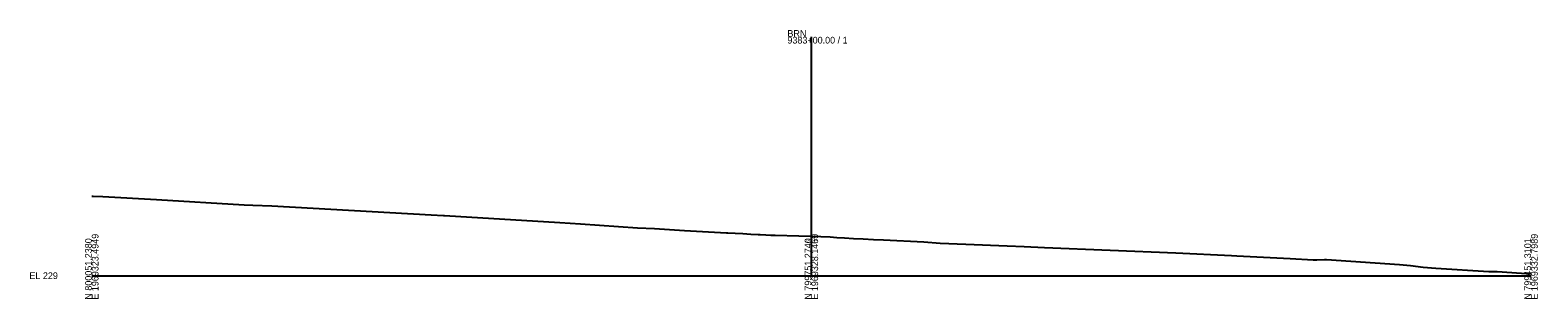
# Model space of a CAD drawing. Extents: x -26 to 2603, y -10 to 49639.
# Drawn here: x 1974 to 2603, y 26490 to 26603 of the extents above; entities that cross this region are included whole.
import ezdxf

# ---------------------------------------------------------------- set-up
doc = ezdxf.new("R2010")
doc.units = 0
for name, color, linetype in [('Default', 7, 'Continuous'), ('RD_GPK_XS_Cell', 7, 'Continuous'), ('RD_XS_ExGround', 7, 'Continuous'), ('RD_XS_TX_Elev_EX', 7, 'Continuous')]:
    doc.layers.add(name, color=color, linetype=linetype)

msp = doc.modelspace()

# ---------------------------------------------------------------- linework, layer by layer
at = {"layer": 'RD_GPK_XS_Cell'}
for p, q in [((2300, 26500), (2300, 26599.72)), ((2000, 26500), (2300, 26500)), ((2300, 26500), (2600, 26500))]:
    msp.add_line(p, q, dxfattribs=at)
at = {"layer": 'RD_XS_ExGround'}
msp.add_lwpolyline([(2000, 26533.24), (2000.58, 26533.21), (2004.66, 26533), (2026.92, 26531.74), (2063.46, 26529.62), (2067.1, 26529.48), (2075.04, 26529.18), (2141.53, 26525.37), (2146.61, 26525.09), (2147.07, 26525.06), (2195.1, 26522.17), (2203.79, 26521.66), (2227.53, 26520.04), (2234.54, 26519.67), (2247.08, 26518.85), (2264.6, 26517.9), (2265.2, 26517.87), (2268.17, 26517.7), (2271.43, 26517.54), (2274.74, 26517.38), (2277.85, 26517.24), (2278.6, 26517.2), (2281.05, 26517.05), (2283.15, 26516.94), (2284.87, 26516.85), (2294.7, 26516.64), (2300, 26516.44), (2307.85, 26516.15), (2310.57, 26515.98), (2313.79, 26515.79), (2317.5, 26515.58), (2321.61, 26515.36), (2325.9, 26515.13), (2330.09, 26514.91), (2346.88, 26514.07), (2353.74, 26513.64), (2364.36, 26513.19), (2381.59, 26512.45), (2388.65, 26512.15), (2397.19, 26511.77), (2451.87, 26509.58), (2475.16, 26508.39), (2477.3, 26508.28), (2499.59, 26507.13), (2509.19, 26506.61), (2510.76, 26506.68), (2513.88, 26506.81), (2514.73, 26506.77), (2545.23, 26504.62), (2549.78, 26504.3), (2555.1, 26503.55), (2560.36, 26503.19), (2582.37, 26501.68), (2583.99, 26501.74), (2584.49, 26501.71), (2585.83, 26501.76), (2600, 26500.72)], dxfattribs=at)

# ---------------------------------------------------------------- texts
at = {"layer": 'Default'}
msp.add_text('-', height=0.0001, dxfattribs=at).set_placement((2000, 26500))
at = {"layer": 'RD_GPK_XS_Cell'}
for s, p in [('9383+00.00 / 1', (2290, 26596.92)), ('BRN', (2290, 26599.72)), ('EL 229', (1974, 26498.6))]:
    msp.add_text(s, height=2.8, dxfattribs=at).set_placement(p)
for s, p in [('N 800051.2380', (2000, 26490)), ('E 1969323.4949', (2002.8, 26490)), ('N 799751.2740', (2300, 26490)), ('E 1969328.1469', (2302.8, 26490)), ('N 799451.3101', (2600, 26490)), ('E 1969332.7989', (2602.8, 26490))]:
    msp.add_text(s, height=2.8, rotation=90, dxfattribs=at).set_placement(p)
at = {"layer": 'RD_XS_TX_Elev_EX'}
msp.add_text('245.44', height=1.2, dxfattribs=at).set_placement((2297.54, 26514.24))

doc.saveas('drawing.dxf')
